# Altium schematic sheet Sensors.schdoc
size 101 x 64 mm
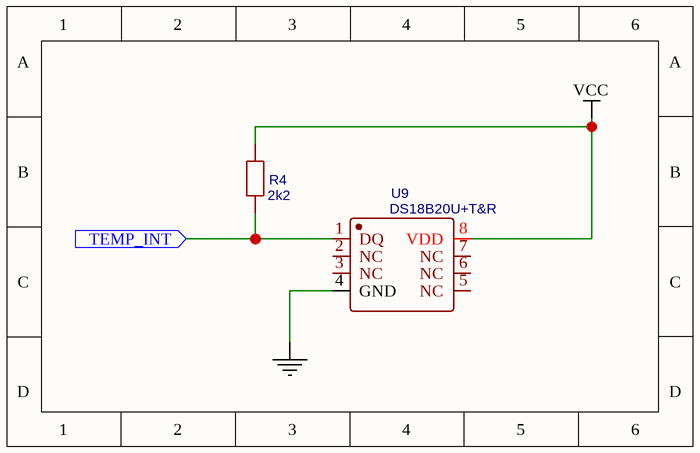
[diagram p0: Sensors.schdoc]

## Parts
R4  2k2  [0603]
U9  DS18B20U+T&R  [USOP-8]

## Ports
TEMP_INT (in)

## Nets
GND: U9.4(GND)
VCC: R4.2 U9.8(VDD)
TEMP_INT: R4.1 U9.1(DQ) ; port TEMP_INT

Not connected (* = marked no-connect by the designer): U9 2(NC) 3(NC) 5(NC) 6(NC) 7(NC)

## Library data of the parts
R4 = 2k2: BOM_Manufacturer Part: TC0325B2201T5E; BOM_Manufacturer: UniOhm; nameAlias: Value(Ω)
U9 = DS18B20U+T&R: BOM_Manufacturer: MAXIM; Contributor: LCSC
